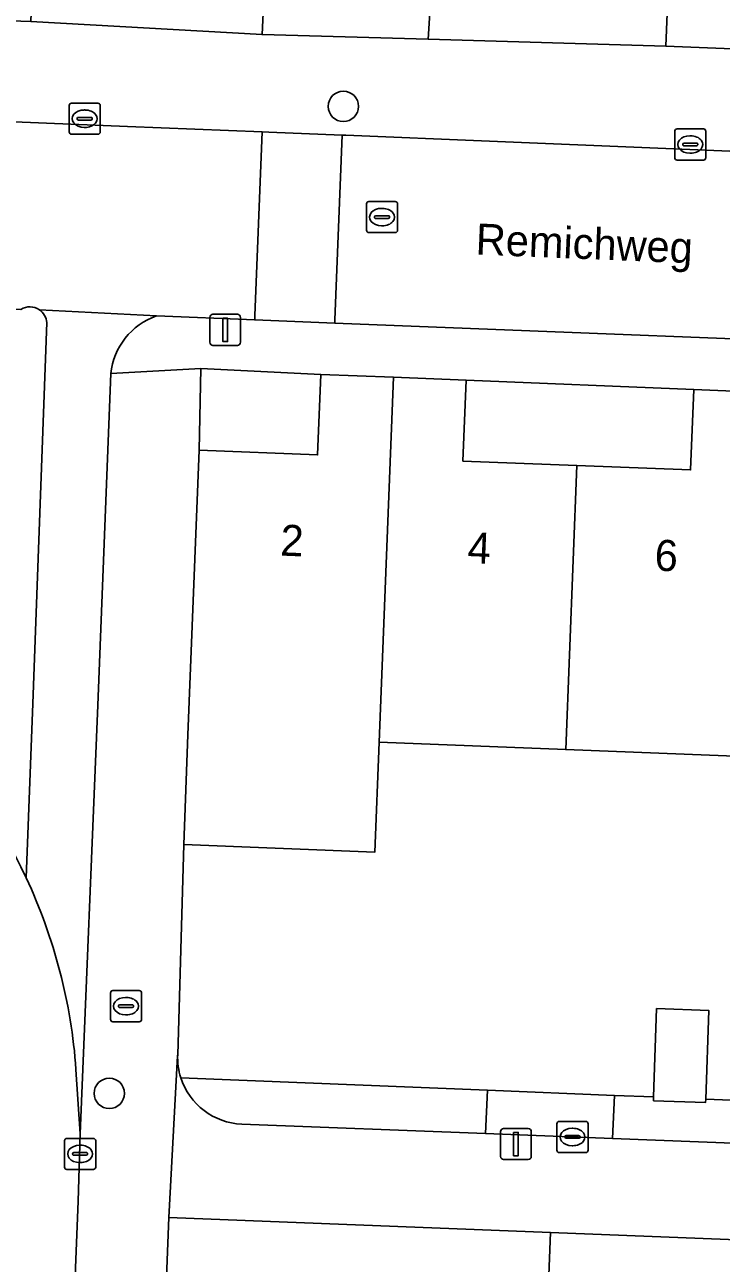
# Model space of a CAD drawing. Extents: x 160786 to 161429, y 386828 to 387485.
# Drawn here: x 161000.13 to 161022.53, y 387264.64 to 387304.46 of the extents above; entities that cross this region are included whole.
import ezdxf

# ---------------------------------------------------------------- set-up
doc = ezdxf.new("R2010")
doc.units = 0
for name, color, linetype in [('IMGEO_Boom', 7, 'Continuous'), ('IMGEO_Brandkraan', 7, 'Continuous'), ('IMGEO_Erf', 7, 'Continuous'), ('IMGEO_Fietspad_open', 7, 'Continuous'), ('IMGEO_Groenvoorziening', 7, 'Continuous'), ('IMGEO_Kolk', 7, 'Continuous'), ('IMGEO_Lichtmast', 7, 'Continuous'), ('IMGEO_Muur', 7, 'Continuous'), ('IMGEO_Openbare_ruimte_label', 7, 'Continuous'), ('IMGEO_Pand', 7, 'Continuous'), ('IMGEO_Pand_nummerreeks', 7, 'Continuous'), ('IMGEO_Rijbaan_lokaal_gesloten', 7, 'Continuous'), ('IMGEO_Rijbaan_lokaal_open', 7, 'Continuous'), ('IMGEO_Rioolput', 7, 'Continuous'), ('IMGEO_Voetpad_open', 7, 'Continuous')]:
    doc.layers.add(name, color=color, linetype=linetype)

msp = doc.modelspace()

# ---------------------------------------------------------------- linework, layer by layer
at = {"layer": 'IMGEO_Boom'}
for centre in [(161010.375, 387301.835), (161002.845, 387270.102)]:
    msp.add_circle(centre, 0.489, dxfattribs=at)
at = {"layer": 'IMGEO_Brandkraan'}
for p, q in [((161002.883, 387272.48), (161002.883, 387273.332)), ((161002.958, 387273.406), (161003.81, 387273.406)), ((161003.884, 387273.332), (161003.884, 387272.48)), ((161003.142, 387272.9), (161003.142, 387272.912)), ((161003.58, 387272.863), (161003.182, 387272.863)), ((161003.185, 387272.949), (161003.583, 387272.949)), ((161003.371, 387273.186), (161003.396, 387273.186)), ((161003.626, 387272.912), (161003.626, 387272.9)), ((161003.81, 387272.406), (161002.958, 387272.406)), ((161003.394, 387272.626), (161003.369, 387272.626))]:
    msp.add_line(p, q, dxfattribs=at)
for points in [[(161002.883, 387272.48), (161002.883, 387273.332)], [(161002.958, 387273.406), (161003.81, 387273.406)], [(161003.884, 387273.332), (161003.884, 387272.48)], [(161003.81, 387272.406), (161002.958, 387272.406)]]:
    msp.add_lwpolyline(points, dxfattribs=at)
for centre, radius, start, end in [((161002.96, 387273.33), 0.0765, 91.552, 178.448), ((161002.96, 387273.33), 0.0765, 91.552, 178.448), ((161003.808, 387273.33), 0.0765, 1.552, 88.448), ((161003.808, 387273.33), 0.0765, 1.552, 88.448), ((161003.182, 387272.909), 0.0403, 85.8775, 175.7526), ((161003.179, 387272.899), 0.0366, 178.938, 274.7102), ((161003.583, 387272.906), 0.043, 264.8664, 352.4533), ((161003.587, 387272.911), 0.0386, 1.7309, 96.639), ((161002.96, 387272.482), 0.0765, 181.552, 268.448), ((161002.96, 387272.482), 0.0765, 181.552, 268.448), ((161003.808, 387272.482), 0.0765, 271.552, 358.448), ((161003.808, 387272.482), 0.0765, 271.552, 358.448)]:
    msp.add_arc(centre, radius, start, end, dxfattribs=at)
for centre, major_axis, ratio, start_param, end_param in [((161003.37, 387272.906), (-0.387, 0.002), 0.722429, 4.712389, 7.853982), ((161003.395, 387272.906), (-0.39, 0.002), 0.717154, 1.570796, 4.712389)]:
    msp.add_ellipse(centre, major_axis=major_axis, ratio=ratio, start_param=start_param, end_param=end_param, dxfattribs=at)
at = {"layer": 'IMGEO_Erf'}
for points in [[(161008.117, 387311.71), (161004.912, 387311.836), (161004.96, 387313.077), (161000.667, 387313.245), (161000.326, 387304.564), (161007.761, 387304.145)], [(161013.104, 387303.992), (161020.754, 387303.772), (161021.106, 387312.451), (161016.805, 387312.626), (161016.756, 387311.404), (161013.577, 387311.533)], [(161005.789, 387293.412), (161005.732, 387290.78), (161009.546, 387290.631), (161009.647, 387293.218)], [(161014.325, 387293.036), (161014.223, 387290.43), (161017.885, 387290.287), (161021.547, 387290.144), (161021.648, 387292.728)]]:
    msp.add_lwpolyline(points, close=True, dxfattribs=at)
for points in [[(161101.692, 387277.875), (161095.739, 387278.107), (161089.782, 387278.339), (161083.812, 387278.572), (161077.787, 387278.807), (161071.808, 387279.04), (161065.781, 387279.275), (161059.712, 387279.512), (161053.612, 387279.75), (161047.514, 387279.988), (161041.541, 387280.221), (161035.537, 387280.455), (161035.313, 387280.464), (161035.188, 387277.258), (161029.377, 387277.484), (161029.502, 387280.69), (161023.521, 387280.923), (161017.529, 387281.157), (161011.527, 387281.391), (161011.389, 387277.862), (161005.238, 387278.102), (161005.045, 387271.345)], [(161005.147, 387270.605), (161015.007, 387270.205), (161019.093, 387270.039), (161020.358, 387269.988), (161020.454, 387272.828), (161022.128, 387272.771), (161022.031, 387269.92), (161027.117, 387269.713), (161029.088, 387269.633), (161029.181, 387272.003), (161033.778, 387271.821), (161033.684, 387269.446), (161039.126, 387269.225), (161042.204, 387269.1)]]:
    msp.add_lwpolyline(points, dxfattribs=at)
msp.add_arc((161007.158, 387271.259), 2.115, 177.6775, 198.0186, dxfattribs=at)
at = {"layer": 'IMGEO_Fietspad_open'}
for points in [[(161004.361, 387295.095), (161000.596, 387295.295)], [(161000.834, 387294.883), (161000.39, 387282.639), (161000.172, 387277.029)], [(161002.473, 387282.585), (161002.899, 387293.241)], [(161001.773, 387270.872), (161001.903, 387268.799), (161002.473, 387282.585)]]:
    msp.add_lwpolyline(points, dxfattribs=at)
for centre, radius, start, end in [((161000.286, 387294.841), 0.549, 4.3435, 55.684), ((161005.076, 387293.028), 2.188, 109.0812, 174.4027), ((160984.397, 387269.64), 17.42, 4.0547, 25.0969)]:
    msp.add_arc(centre, radius, start, end, dxfattribs=at)
at = {"layer": 'IMGEO_Groenvoorziening'}
msp.add_lwpolyline([(161007.11, 387269.114), (161014.949, 387268.809), (161015.007, 387270.205), (161005.147, 387270.605)], dxfattribs=at)
msp.add_lwpolyline([(161027.117, 387269.713), (161022.031, 387269.92), (161022.027, 387269.811), (161020.354, 387269.867), (161020.358, 387269.988), (161019.093, 387270.039), (161019.035, 387268.65), (161027.059, 387268.338)], close=True, dxfattribs=at)
msp.add_arc((161007.194, 387271.262), 2.15, 197.7954, 267.7675, dxfattribs=at)
at = {"layer": 'IMGEO_Kolk'}
for p, q in [((161001.628, 387301.938), (161002.48, 387301.938)), ((161001.553, 387301.012), (161001.553, 387301.864)), ((161001.855, 387301.481), (161002.253, 387301.481)), ((161002.041, 387301.718), (161002.066, 387301.718)), ((161002.554, 387301.864), (161002.554, 387301.012)), ((161001.812, 387301.432), (161001.812, 387301.444)), ((161002.25, 387301.395), (161001.852, 387301.395)), ((161002.064, 387301.158), (161002.039, 387301.158)), ((161002.296, 387301.444), (161002.296, 387301.432)), ((161021.11, 387301.108), (161021.962, 387301.108)), ((161002.48, 387300.938), (161001.628, 387300.938)), ((161021.035, 387300.182), (161021.035, 387301.034)), ((161021.523, 387300.888), (161021.548, 387300.888)), ((161022.036, 387301.034), (161022.036, 387300.182)), ((161021.294, 387300.602), (161021.294, 387300.614)), ((161021.732, 387300.565), (161021.334, 387300.565)), ((161021.337, 387300.651), (161021.735, 387300.651)), ((161021.546, 387300.328), (161021.521, 387300.328)), ((161021.778, 387300.614), (161021.778, 387300.602)), ((161021.962, 387300.108), (161021.11, 387300.108)), ((161017.246, 387268.274), (161017.246, 387269.126)), ((161017.321, 387269.2), (161018.173, 387269.2)), ((161017.734, 387268.98), (161017.759, 387268.98)), ((161018.247, 387269.126), (161018.247, 387268.274)), ((161001.406, 387267.73), (161001.406, 387268.582)), ((161001.481, 387268.656), (161002.333, 387268.656)), ((161001.894, 387268.436), (161001.919, 387268.436)), ((161002.407, 387268.582), (161002.407, 387267.73)), ((161017.505, 387268.694), (161017.505, 387268.706)), ((161017.943, 387268.657), (161017.545, 387268.657)), ((161017.548, 387268.743), (161017.946, 387268.743)), ((161017.757, 387268.42), (161017.732, 387268.42)), ((161017.989, 387268.706), (161017.989, 387268.694)), ((161001.665, 387268.15), (161001.665, 387268.162)), ((161002.103, 387268.113), (161001.705, 387268.113)), ((161001.708, 387268.199), (161002.106, 387268.199)), ((161002.149, 387268.162), (161002.149, 387268.15)), ((161018.173, 387268.2), (161017.321, 387268.2)), ((161002.333, 387267.656), (161001.481, 387267.656)), ((161001.917, 387267.876), (161001.892, 387267.876))]:
    msp.add_line(p, q, dxfattribs=at)
for points in [[(161001.628, 387301.938), (161002.48, 387301.938)], [(161001.553, 387301.012), (161001.553, 387301.864)], [(161002.554, 387301.864), (161002.554, 387301.012)], [(161021.11, 387301.108), (161021.962, 387301.108)], [(161002.48, 387300.938), (161001.628, 387300.938)], [(161021.035, 387300.182), (161021.035, 387301.034)], [(161022.036, 387301.034), (161022.036, 387300.182)], [(161021.962, 387300.108), (161021.11, 387300.108)], [(161017.246, 387268.274), (161017.246, 387269.126)], [(161017.321, 387269.2), (161018.173, 387269.2)], [(161018.247, 387269.126), (161018.247, 387268.274)], [(161001.406, 387267.73), (161001.406, 387268.582)], [(161001.481, 387268.656), (161002.333, 387268.656)], [(161002.407, 387268.582), (161002.407, 387267.73)], [(161018.173, 387268.2), (161017.321, 387268.2)], [(161002.333, 387267.656), (161001.481, 387267.656)]]:
    msp.add_lwpolyline(points, dxfattribs=at)
for centre, radius, start, end in [((161001.63, 387301.862), 0.0765, 91.552, 178.448), ((161001.63, 387301.862), 0.0765, 91.552, 178.448), ((161002.478, 387301.862), 0.0765, 1.552, 88.448), ((161002.478, 387301.862), 0.0765, 1.552, 88.448), ((161001.852, 387301.441), 0.0403, 85.8775, 175.7526), ((161002.257, 387301.443), 0.0386, 1.7309, 96.639), ((161001.849, 387301.431), 0.0366, 178.938, 274.7102), ((161002.253, 387301.438), 0.043, 264.8664, 352.4533), ((161021.112, 387301.032), 0.0765, 91.552, 178.448), ((161021.112, 387301.032), 0.0765, 91.552, 178.448), ((161021.96, 387301.032), 0.0765, 1.552, 88.448), ((161021.96, 387301.032), 0.0765, 1.552, 88.448), ((161001.63, 387301.014), 0.0765, 181.552, 268.448), ((161001.63, 387301.014), 0.0765, 181.552, 268.448), ((161002.478, 387301.014), 0.0765, 271.552, 358.448), ((161002.478, 387301.014), 0.0765, 271.552, 358.448), ((161021.334, 387300.611), 0.0403, 85.8775, 175.7526), ((161021.331, 387300.601), 0.0366, 178.938, 274.7102), ((161021.735, 387300.608), 0.043, 264.8664, 352.4533), ((161021.739, 387300.613), 0.0386, 1.7309, 96.639), ((161021.112, 387300.184), 0.0765, 181.552, 268.448), ((161021.112, 387300.184), 0.0765, 181.552, 268.448), ((161021.96, 387300.184), 0.0765, 271.552, 358.448), ((161021.96, 387300.184), 0.0765, 271.552, 358.448), ((161017.323, 387269.124), 0.0765, 91.552, 178.448), ((161017.323, 387269.124), 0.0765, 91.552, 178.448), ((161018.171, 387269.124), 0.0765, 1.552, 88.448), ((161018.171, 387269.124), 0.0765, 1.552, 88.448), ((161001.483, 387268.58), 0.0765, 91.552, 178.448), ((161001.483, 387268.58), 0.0765, 91.552, 178.448), ((161002.331, 387268.58), 0.0765, 1.552, 88.448), ((161002.331, 387268.58), 0.0765, 1.552, 88.448), ((161017.545, 387268.703), 0.0403, 85.8775, 175.7526), ((161017.542, 387268.693), 0.0366, 178.938, 274.7102), ((161017.946, 387268.7), 0.043, 264.8664, 352.4533), ((161017.95, 387268.705), 0.0386, 1.7309, 96.639), ((161001.705, 387268.159), 0.0403, 85.8775, 175.7526), ((161001.702, 387268.149), 0.0366, 178.938, 274.7102), ((161002.106, 387268.156), 0.043, 264.8664, 352.4533), ((161002.11, 387268.161), 0.0386, 1.7309, 96.639), ((161017.323, 387268.276), 0.0765, 181.552, 268.448), ((161017.323, 387268.276), 0.0765, 181.552, 268.448), ((161018.171, 387268.276), 0.0765, 271.552, 358.448), ((161018.171, 387268.276), 0.0765, 271.552, 358.448), ((161001.483, 387267.732), 0.0765, 181.552, 268.448), ((161001.483, 387267.732), 0.0765, 181.552, 268.448), ((161002.331, 387267.732), 0.0765, 271.552, 358.448), ((161002.331, 387267.732), 0.0765, 271.552, 358.448)]:
    msp.add_arc(centre, radius, start, end, dxfattribs=at)
for centre, major_axis, ratio, start_param, end_param in [((161002.04, 387301.438), (-0.387, 0.002), 0.722429, 4.712389, 7.853982), ((161002.065, 387301.438), (-0.39, 0.002), 0.717154, 1.570796, 4.712389), ((161021.522, 387300.608), (-0.387, 0.002), 0.722429, 4.712389, 7.853982), ((161021.547, 387300.608), (-0.39, 0.002), 0.717154, 1.570796, 4.712389), ((161017.733, 387268.7), (-0.387, 0.002), 0.722429, 4.712389, 7.853982), ((161017.758, 387268.7), (-0.39, 0.002), 0.717154, 1.570796, 4.712389), ((161001.893, 387268.156), (-0.387, 0.002), 0.722429, 4.712389, 7.853982), ((161001.918, 387268.156), (-0.39, 0.002), 0.717154, 1.570796, 4.712389)]:
    msp.add_ellipse(centre, major_axis=major_axis, ratio=ratio, start_param=start_param, end_param=end_param, dxfattribs=at)
at = {"layer": 'IMGEO_Lichtmast'}
for p, q in [((161006.178, 387295.149), (161006.968, 387295.149)), ((161006.968, 387295.149), (161006.178, 387295.149)), ((161006.078, 387294.249), (161006.078, 387295.049)), ((161006.078, 387295.049), (161006.078, 387294.249)), ((161007.068, 387295.049), (161007.068, 387294.249)), ((161007.068, 387294.249), (161007.068, 387295.049)), ((161006.968, 387294.149), (161006.178, 387294.149)), ((161006.178, 387294.149), (161006.968, 387294.149)), ((161015.43, 387268.074), (161015.43, 387268.874)), ((161015.43, 387268.874), (161015.43, 387268.074)), ((161015.53, 387268.974), (161016.32, 387268.974)), ((161016.32, 387268.974), (161015.53, 387268.974)), ((161016.42, 387268.874), (161016.42, 387268.074)), ((161016.42, 387268.074), (161016.42, 387268.874)), ((161016.32, 387267.974), (161015.53, 387267.974)), ((161015.53, 387267.974), (161016.32, 387267.974))]:
    msp.add_line(p, q, dxfattribs=at)
for points in [[(161006.498, 387295.024), (161006.648, 387295.024), (161006.648, 387294.274), (161006.498, 387294.274), (161006.498, 387295.024)], [(161015.85, 387268.849), (161016, 387268.849), (161016, 387268.099), (161015.85, 387268.099), (161015.85, 387268.849)]]:
    msp.add_lwpolyline(points, dxfattribs=at)
for centre, start, end in [((161006.178, 387295.049), 90, 180), ((161006.178, 387295.049), 90, 180), ((161006.968, 387295.049), 0, 90), ((161006.968, 387295.049), 360, 90), ((161006.178, 387294.249), 180, 270), ((161006.178, 387294.249), 180, 270), ((161006.968, 387294.249), 270, 0), ((161006.968, 387294.249), 270, 0), ((161015.53, 387268.874), 90, 180), ((161015.53, 387268.874), 90, 180), ((161016.32, 387268.874), 0, 90), ((161016.32, 387268.874), 360, 90), ((161015.53, 387268.074), 180, 270), ((161015.53, 387268.074), 180, 270), ((161016.32, 387268.074), 270, 0), ((161016.32, 387268.074), 270, 0)]:
    msp.add_arc(centre, 0.1, start, end, dxfattribs=at)
at = {"layer": 'IMGEO_Muur'}
for points in [[(161000.326, 387304.564), (161007.761, 387304.145), (161008.117, 387311.71)], [(161013.577, 387311.533), (161013.104, 387303.992)], [(161013.104, 387303.992), (161020.754, 387303.772)]]:
    msp.add_lwpolyline(points, dxfattribs=at)
at = {"layer": 'IMGEO_Pand'}
for points in [[(161025.572, 387303.577), (161026.033, 387315.194), (161021.298, 387315.375), (161013.745, 387315.68), (161013.577, 387311.533), (161016.756, 387311.404), (161016.805, 387312.626), (161021.106, 387312.451), (161020.754, 387303.772)], [(161011.985, 387293.127), (161009.647, 387293.218), (161009.546, 387290.631), (161005.732, 387290.78), (161005.376, 387281.631), (161005.238, 387278.102), (161011.389, 387277.862), (161011.527, 387281.391)], [(161011.985, 387293.127), (161011.527, 387281.391), (161017.529, 387281.157), (161017.885, 387290.287), (161014.223, 387290.43), (161014.325, 387293.036)], [(161021.648, 387292.728), (161021.547, 387290.144), (161017.885, 387290.287), (161017.529, 387281.157), (161023.521, 387280.923), (161023.978, 387292.637)], [(161020.358, 387269.988), (161020.354, 387269.867), (161022.027, 387269.811), (161022.031, 387269.92), (161022.128, 387272.771), (161020.454, 387272.828)], [(161004.762, 387266.114), (161004.599, 387261.982), (161007.782, 387261.856), (161007.834, 387263.176), (161012.08, 387263.009), (161011.744, 387254.512), (161016.598, 387254.354), (161017.04, 387265.629)], [(161017.04, 387265.629), (161016.598, 387254.354), (161021.539, 387254.196), (161021.872, 387262.624), (161026.12, 387262.457), (161026.068, 387261.131), (161029.154, 387261.009), (161029.318, 387265.143)]]:
    msp.add_lwpolyline(points, close=True, dxfattribs=at)
at = {"layer": 'IMGEO_Rijbaan_lokaal_gesloten'}
for points in [[(161000.172, 387277.029), (161000, 387277.385), (160999.845, 387277.687), (160999.02, 387279.112), (160998.072, 387280.457), (160997.006, 387281.713), (160995.833, 387282.868), (160995.342, 387283.295), (160994.149, 387284.206), (160992.88, 387285.007), (160991.544, 387285.692), (160990.716, 387286.044), (160988.756, 387286.659)], [(160996.658, 387175.171), (160995.922, 387165.873), (160993.223, 387100.345), (160995.117, 387100.282), (160995.759, 387116.531), (160996.02, 387123.147), (160996.876, 387144.816), (160997.133, 387151.331), (160997.56, 387162.14), (160998.791, 387192.018), (160998.93, 387196.297), (160999.473, 387210.041), (161000, 387223.379), (161001.181, 387250), (161001.845, 387266.642), (161001.903, 387268.799), (161001.773, 387270.872)]]:
    msp.add_lwpolyline(points, dxfattribs=at)
msp.add_arc((160984.397, 387269.64), 17.42, 4.0547, 25.0969, dxfattribs=at)
at = {"layer": 'IMGEO_Rijbaan_lokaal_open'}
for points in [[(161007.761, 387301.014), (161003.427, 387301.192), (160944.555, 387303.604), (160944.327, 387297.514), (160946.729, 387297.437), (161000, 387295.308)], [(161000.596, 387295.295), (161004.361, 387295.095), (161007.523, 387294.97), (161007.529, 387295.113), (161007.761, 387301.014)]]:
    msp.add_lwpolyline(points, dxfattribs=at)
for points in [[(161010.337, 387300.909), (161007.976, 387301.005), (161007.761, 387301.014), (161007.529, 387295.113), (161007.523, 387294.97), (161010.099, 387294.869), (161010.103, 387294.968)], [(161031.068, 387300.048), (161015.08, 387300.714), (161010.458, 387300.904), (161010.337, 387300.909), (161010.103, 387294.968), (161010.099, 387294.869), (161030.833, 387294.053), (161030.837, 387294.156)]]:
    msp.add_lwpolyline(points, close=True, dxfattribs=at)
msp.add_arc((161000.288, 387294.841), 0.549, 55.8336, 121.6673, dxfattribs=at)
at = {"layer": 'IMGEO_Rioolput'}
for p, q in [((161011.119, 387297.85), (161011.119, 387298.702)), ((161011.194, 387298.776), (161012.046, 387298.776)), ((161012.12, 387298.702), (161012.12, 387297.85)), ((161011.378, 387298.27), (161011.378, 387298.282)), ((161011.421, 387298.319), (161011.819, 387298.319)), ((161011.607, 387298.556), (161011.632, 387298.556)), ((161011.862, 387298.282), (161011.862, 387298.27)), ((161011.816, 387298.233), (161011.418, 387298.233)), ((161011.63, 387297.996), (161011.605, 387297.996)), ((161012.046, 387297.776), (161011.194, 387297.776))]:
    msp.add_line(p, q, dxfattribs=at)
for points in [[(161011.119, 387297.85), (161011.119, 387298.702)], [(161011.194, 387298.776), (161012.046, 387298.776)], [(161012.12, 387298.702), (161012.12, 387297.85)], [(161012.046, 387297.776), (161011.194, 387297.776)]]:
    msp.add_lwpolyline(points, dxfattribs=at)
for centre, radius, start, end in [((161011.196, 387298.7), 0.0765, 91.552, 178.448), ((161011.196, 387298.7), 0.0765, 91.552, 178.448), ((161012.044, 387298.7), 0.0765, 1.552, 88.448), ((161012.044, 387298.7), 0.0765, 1.552, 88.448), ((161011.418, 387298.279), 0.0403, 85.8775, 175.7526), ((161011.823, 387298.281), 0.0386, 1.7309, 96.639), ((161011.415, 387298.269), 0.0366, 178.938, 274.7102), ((161011.819, 387298.276), 0.043, 264.8664, 352.4533), ((161011.196, 387297.852), 0.0765, 181.552, 268.448), ((161011.196, 387297.852), 0.0765, 181.552, 268.448), ((161012.044, 387297.852), 0.0765, 271.552, 358.448), ((161012.044, 387297.852), 0.0765, 271.552, 358.448)]:
    msp.add_arc(centre, radius, start, end, dxfattribs=at)
for centre, major_axis, ratio, start_param, end_param in [((161011.606, 387298.276), (-0.387, 0.002), 0.722429, 4.712389, 7.853982), ((161011.631, 387298.276), (-0.39, 0.002), 0.717154, 1.570796, 4.712389)]:
    msp.add_ellipse(centre, major_axis=major_axis, ratio=ratio, start_param=start_param, end_param=end_param, dxfattribs=at)
at = {"layer": 'IMGEO_Voetpad_open'}
for points in [[(161014.22, 387326.967), (161014.47, 387334.14), (161014.629, 387338.054), (161014.881, 387344.271), (161009.396, 387344.491), (161009.145, 387338.11), (161008.998, 387334.368), (161008.672, 387327.188), (161008.507, 387322.987), (161008.28, 387315.875), (161008.117, 387311.71), (161007.761, 387304.145), (161013.104, 387303.992), (161013.577, 387311.533), (161013.745, 387315.68), (161014.049, 387322.75)], [(161019.093, 387270.039), (161015.007, 387270.205), (161014.949, 387268.809), (161019.035, 387268.65)]]:
    msp.add_lwpolyline(points, close=True, dxfattribs=at)
for points in [[(161030.392, 387303.382), (161025.572, 387303.577), (161020.754, 387303.772), (161013.104, 387303.992), (161007.761, 387304.145), (161000.326, 387304.564), (161000, 387304.577), (160995.34, 387304.76), (160990.678, 387304.943), (160983.144, 387305.21), (160977.765, 387305.618), (160970.332, 387305.758), (160965.498, 387305.923), (160960.665, 387306.088), (160953.082, 387306.333), (160949.797, 387306.515), (160949.619, 387306.518), (160946.741, 387306.626), (160943.863, 387306.734)], [(160941.896, 387303.713), (160942.394, 387303.693), (160943.923, 387303.63), (160944.555, 387303.604), (161003.427, 387301.192), (161007.761, 387301.014), (161007.976, 387301.005), (161010.337, 387300.909), (161010.458, 387300.904), (161015.08, 387300.714), (161031.068, 387300.048), (161031.396, 387300.034), (161033.794, 387299.932), (161033.89, 387299.928), (161041.191, 387299.617)], [(160950.61, 387288.321), (160950.799, 387288.308), (160986.494, 387286.962), (160988.228, 387286.774), (160988.756, 387286.659), (160990.716, 387286.044), (160991.544, 387285.692), (160992.88, 387285.007), (160994.149, 387284.206), (160995.342, 387283.295), (160995.833, 387282.868), (160997.006, 387281.713), (160998.072, 387280.457), (160999.02, 387279.112), (160999.845, 387277.687), (161000, 387277.385), (161000.172, 387277.029), (161000.39, 387282.639), (161000.834, 387294.883)], [(161030.833, 387294.053), (161010.099, 387294.869), (161007.523, 387294.97), (161004.361, 387295.095)], [(161004.599, 387261.982), (161004.762, 387266.114), (161005.038, 387271.31), (161005.045, 387271.345), (161005.238, 387278.102), (161005.376, 387281.631), (161005.732, 387290.78), (161005.789, 387293.412), (161002.899, 387293.241), (161002.473, 387282.585), (161001.903, 387268.799), (161001.845, 387266.642), (161001.181, 387250)], [(161002.899, 387293.241), (161005.789, 387293.412), (161009.647, 387293.218), (161011.985, 387293.127), (161014.325, 387293.036), (161021.648, 387292.728), (161023.978, 387292.637), (161026.304, 387292.547), (161033.611, 387292.22), (161035.992, 387292.127), (161038.374, 387292.034), (161045.615, 387291.726)], [(161005.045, 387271.345), (161005.038, 387271.31), (161004.762, 387266.114), (161017.04, 387265.629), (161029.318, 387265.143), (161029.154, 387261.009)], [(161041.819, 387250.786), (161041.992, 387254.976), (161042.243, 387259.778), (161042.242, 387259.789), (161042.15, 387267.701), (161039.07, 387267.871), (161031.266, 387268.175), (161030.819, 387268.192), (161027.059, 387268.338), (161019.035, 387268.65), (161014.949, 387268.809), (161007.11, 387269.114)]]:
    msp.add_lwpolyline(points, dxfattribs=at)
for centre, radius, start, end in [((161000.288, 387294.841), 0.549, 55.8336, 121.6673), ((161000.286, 387294.841), 0.549, 4.3435, 55.684), ((161005.076, 387293.028), 2.188, 109.0812, 174.4027), ((161007.158, 387271.259), 2.115, 177.6775, 198.0186), ((161007.194, 387271.262), 2.15, 197.7954, 267.7675)]:
    msp.add_arc(centre, radius, start, end, dxfattribs=at)

# ---------------------------------------------------------------- texts
at = {"layer": 'IMGEO_Openbare_ruimte_label'}
msp.add_text('Remichweg', height=1, rotation=357.6498, dxfattribs=at).set_placement((161014.618, 387297.073))
at = {"layer": 'IMGEO_Pand_nummerreeks'}
for s, rotation, p in [('2', 357.7082, (161008.334, 387287.393)), ('4', 357.7109, (161014.356, 387287.152)), ('6', 357.7109, (161020.375, 387286.912))]:
    msp.add_text(s, height=1, rotation=rotation, dxfattribs=at).set_placement(p)

doc.saveas('drawing.dxf')
